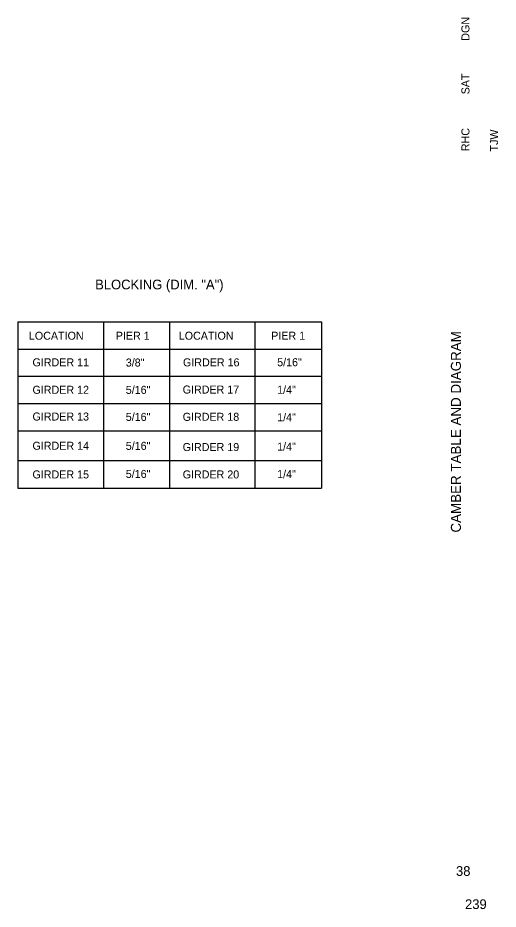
# Model space of a CAD drawing. Extents: x 4.1 to 33.4, y -25.9 to 16.7.
# Drawn here: x 25.01 to 33.41, y 1.08 to 16.68 of the extents above; entities that cross this region are included whole.
import ezdxf

# ---------------------------------------------------------------- set-up
doc = ezdxf.new("R2010")
doc.units = 0
doc.layers.add('BR_X_Slab_Const_Joint', color=7, linetype='Continuous')
doc.layers.add('SH_Border', color=7, linetype='Continuous')

msp = doc.modelspace()

# ---------------------------------------------------------------- linework, layer by layer
at = {"layer": 'BR_X_Slab_Const_Joint'}
for p, q in [((25.007, 11.357), (30.315, 11.357)), ((25.007, 11.357), (25.007, 8.451)), ((26.506, 11.357), (26.506, 10.878)), ((27.661, 11.357), (27.661, 10.878)), ((29.151, 11.357), (29.151, 10.878)), ((30.315, 11.357), (30.315, 8.451)), ((25.007, 10.878), (30.315, 10.878)), ((26.506, 10.878), (26.506, 10.41)), ((27.661, 10.878), (27.661, 10.41)), ((29.151, 10.878), (29.151, 10.41)), ((25.007, 10.41), (30.315, 10.41)), ((26.506, 10.41), (26.506, 9.93)), ((27.661, 10.41), (27.661, 9.93)), ((29.151, 10.41), (29.151, 9.93)), ((25.007, 9.93), (30.315, 9.93)), ((26.506, 9.93), (26.506, 9.451)), ((27.661, 9.93), (27.661, 9.451)), ((29.151, 9.93), (29.151, 9.451)), ((25.007, 9.451), (26.506, 9.451)), ((26.506, 9.451), (30.315, 9.451)), ((26.506, 9.451), (26.506, 8.93)), ((27.661, 9.451), (27.661, 8.93)), ((29.151, 9.451), (29.151, 8.93)), ((25.007, 8.93), (30.315, 8.93)), ((26.506, 8.93), (26.506, 8.451)), ((27.661, 8.93), (27.661, 8.451)), ((29.151, 8.93), (29.151, 8.451)), ((25.007, 8.451), (30.315, 8.451))]:
    msp.add_line(p, q, dxfattribs=at)

# ---------------------------------------------------------------- texts
for s, height, p in [(' BLOCKING (DIM. "A") ', 0.17, (26.295, 11.927)), ('LOCATION', 0.14, (25.2, 11.046)), ('PIER 1', 0.14, (26.719, 11.046)), ('LOCATION', 0.14, (27.821, 11.046)), ('PIER 1', 0.14, (29.437, 11.046)), ('GIRDER 11', 0.14, (25.263, 10.58)), ('3/8"', 0.14, (26.894, 10.577)), ('GIRDER 16', 0.14, (27.894, 10.58)), ('5/16"', 0.14, (29.541, 10.582)), ('GIRDER 12', 0.14, (25.263, 10.1)), ('5/16"', 0.14, (26.894, 10.099)), ('GIRDER 17', 0.14, (27.889, 10.104)), ('1/4"', 0.14, (29.541, 10.101)), ('GIRDER 13', 0.14, (25.263, 9.632)), ('5/16"', 0.14, (26.894, 9.626)), ('GIRDER 18', 0.14, (27.889, 9.627)), ('1/4"', 0.14, (29.541, 9.619)), ('GIRDER 14', 0.14, (25.263, 9.121)), ('5/16"', 0.14, (26.894, 9.119)), ('GIRDER 19', 0.14, (27.889, 9.098)), ('1/4"', 0.14, (29.541, 9.107)), ('GIRDER 15', 0.14, (25.263, 8.619)), ('5/16"', 0.14, (26.894, 8.628)), ('GIRDER 20', 0.14, (27.889, 8.619)), ('1/4"', 0.14, (29.541, 8.625)), ('38', 0.17, (32.668, 1.665)), ('239', 0.17, (32.826, 1.085))]:
    msp.add_text(s, height=height, dxfattribs=at).set_placement(p)
at = {"layer": 'SH_Border'}
for s, height, p in [('DGN', 0.14, (32.903, 16.277)), ('SAT', 0.14, (32.903, 15.339)), ('RHC', 0.14, (32.903, 14.345)), ('TJW', 0.14, (33.403, 14.339)), ('CAMBER TABLE AND DIAGRAM', 0.175, (32.754, 7.672))]:
    msp.add_text(s, height=height, rotation=90, dxfattribs=at).set_placement(p)

doc.saveas('drawing.dxf')
